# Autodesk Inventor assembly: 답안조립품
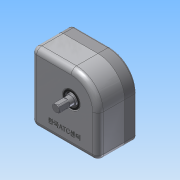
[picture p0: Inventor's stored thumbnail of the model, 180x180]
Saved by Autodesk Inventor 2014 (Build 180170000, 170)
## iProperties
Created: 2015-11
Part Number: 답안조립품
Document SubType Name: Assembly
Designer: net
Author: net
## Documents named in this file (13)
- C:\Users\net\Desktop\Inventor2급-박유나\답안조립품.iam
- C:\Users\net\Desktop\Inventor2급-박유나\본체.ipt
- C:\Users\net\Desktop\Inventor2급-박유나\베어링 6002.ipt
- C:\Users\net\Desktop\Inventor2급-박유나\베어링 6001.ipt
- C:\Users\net\Desktop\Inventor2급-박유나\편심 축.ipt
- C:\Users\net\Desktop\Inventor2급-박유나\로드 축.ipt
- C:\Users\net\Desktop\Inventor2급-박유나\로드.ipt
- C:\Users\net\Desktop\Inventor2급-박유나\앞커버.ipt
- C:\Users\net\Desktop\Inventor2급-박유나\오일실 15 x 25.ipt
- C:\Users\net\Desktop\Inventor2급-박유나\오일실 12 x 22.ipt
- C:\Users\net\Desktop\Inventor2급-박유나\M3 x 0.5.ipt
- C:\Users\net\Desktop\Inventor2급-박유나\축 커버.ipt
- C:\Users\net\Desktop\Inventor2급-박유나\M4 x 0.7.ipt
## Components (9 placed, 2 different names)
1. M4 x 0.7:5
2. M3 x 0.5:1
3. M3 x 0.5:2
4. M3 x 0.5:3
5. M3 x 0.5:4
6. M4 x 0.7:1
7. M4 x 0.7:2
8. M4 x 0.7:3
9. M4 x 0.7:4
